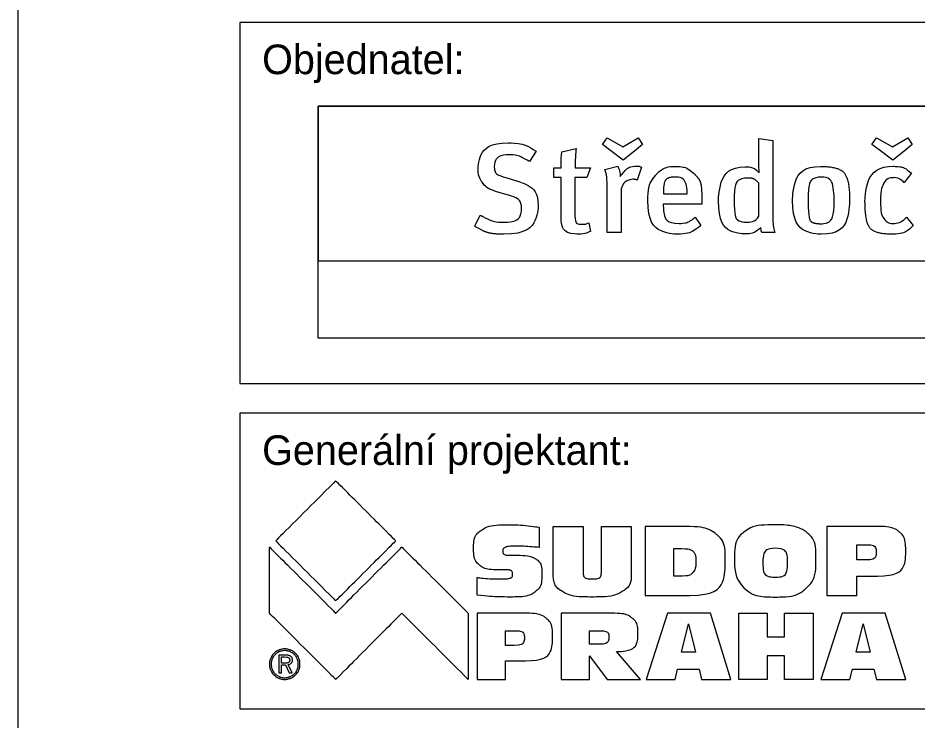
# Model space of a CAD drawing. Extents: x 1619 to 1829, y 760 to 1057.
# Drawn here: x 1618.7 to 1679.4, y 860.7 to 908.2 of the extents above; entities that cross this region are included whole.
import ezdxf

# ---------------------------------------------------------------- set-up
doc = ezdxf.new("R2010")
doc.units = 0
doc.layers.add('102_ZPEVNENI', color=7, linetype='Continuous')
doc.layers.add('120_ZPEVNENI', color=7, linetype='Continuous')

msp = doc.modelspace()

# ---------------------------------------------------------------- linework, layer by layer
at = {"layer": '102_ZPEVNENI'}
for points in [[(1663.73, 873.782), (1661.043, 873.782), (1661.043, 869.128), (1664.09, 869.128)], [(1676.82, 873.782), (1673.326, 873.782), (1673.326, 869.128), (1675.345, 869.128), (1675.345, 870.436), (1676.74, 870.436)], [(1663.563, 870.432), (1662.971, 870.432), (1662.971, 872.286), (1663.498, 872.286)], [(1675.943, 871.522), (1675.345, 871.522), (1675.345, 872.551), (1676.044, 872.551)], [(1653.025, 867.92), (1649.678, 867.92), (1649.678, 863.446), (1651.612, 863.446), (1651.612, 864.703), (1652.949, 864.703)], [(1658.766, 867.92), (1655.36, 867.92), (1655.36, 863.446), (1657.286, 863.446), (1657.286, 865.031), (1658.472, 863.446), (1660.73, 863.446), (1659.105, 865.333)], [(1663.063, 863.446), (1663.232, 864.143), (1664.695, 864.143), (1664.857, 863.446), (1666.838, 863.446), (1665.457, 867.92), (1662.546, 867.92), (1661.11, 863.446), (1663.063, 863.446)], [(1674.876, 863.446), (1675.045, 864.143), (1676.508, 864.143), (1676.67, 863.446), (1678.65, 863.446), (1677.27, 867.92), (1674.358, 867.92), (1672.923, 863.446), (1674.876, 863.446)], [(1663.97, 867.204), (1664.436, 865.28), (1663.498, 865.28), (1663.97, 867.204)], [(1675.783, 867.204), (1676.249, 865.28), (1675.31, 865.28), (1675.783, 867.204)], [(1652.185, 865.748), (1651.612, 865.748), (1651.612, 866.737), (1652.282, 866.737)], [(1657.929, 865.821), (1657.286, 865.821), (1657.286, 866.737), (1657.953, 866.737)], [(1636.709, 865.084), (1636.275, 865.084), (1636.275, 863.899), (1636.453, 863.899), (1636.453, 864.42), (1636.73, 864.42), (1636.98, 863.899), (1637.184, 863.899), (1636.92, 864.445)], [(1636.675, 864.538), (1636.453, 864.538), (1636.453, 864.963), (1636.675, 864.963)]]:
    msp.add_lwpolyline(points, dxfattribs=at)
for points in [[(1636.07, 872.814), (1636.07, 872.814), (1640.125, 876.869), (1640.125, 876.869), (1640.125, 876.869), (1640.125, 876.869), (1644.18, 872.814), (1644.18, 872.814), (1644.18, 872.814), (1644.18, 872.814), (1640.125, 868.759), (1640.125, 868.759), (1640.125, 868.759), (1640.125, 868.759), (1636.07, 872.814), (1636.07, 872.814)], [(1649.678, 869.147), (1650.405, 869.06), (1651.168, 869.016), (1651.968, 869.016), (1651.968, 869.016), (1652.733, 869.016), (1653.272, 869.129), (1653.584, 869.354), (1653.584, 869.354), (1653.899, 869.579), (1654.056, 869.967), (1654.056, 870.519), (1654.056, 870.519), (1654.056, 871.058), (1653.915, 871.418), (1653.631, 871.598), (1653.631, 871.598), (1653.365, 871.759), (1652.824, 871.84), (1652.007, 871.84), (1652.007, 871.84), (1651.616, 871.84), (1651.421, 871.932), (1651.421, 872.117), (1651.421, 872.117), (1651.421, 872.234), (1651.478, 872.319), (1651.593, 872.372), (1651.593, 872.372), (1651.711, 872.425), (1651.916, 872.451), (1652.209, 872.451), (1652.209, 872.451), (1652.706, 872.451), (1653.251, 872.423), (1653.87, 872.366), (1653.87, 872.366), (1653.87, 872.366), (1653.87, 873.738), (1653.87, 873.738), (1653.87, 873.738), (1653.131, 873.842), (1652.439, 873.894), (1651.77, 873.894), (1651.77, 873.894), (1650.927, 873.894), (1650.329, 873.774), (1649.977, 873.534), (1649.977, 873.534), (1649.624, 873.296), (1649.447, 872.916), (1649.447, 872.394), (1649.447, 872.394), (1649.447, 871.815), (1649.573, 871.413), (1649.825, 871.191), (1649.825, 871.191), (1650.08, 870.968), (1650.502, 870.858), (1651.093, 870.863), (1651.093, 870.863), (1651.093, 870.863), (1651.586, 870.863), (1651.586, 870.863), (1651.586, 870.863), (1651.759, 870.863), (1651.885, 870.844), (1651.964, 870.806), (1651.964, 870.806), (1652.043, 870.767), (1652.083, 870.684), (1652.083, 870.557), (1652.083, 870.557), (1652.083, 870.424), (1652.031, 870.337), (1651.928, 870.299), (1651.928, 870.299), (1651.827, 870.261), (1651.657, 870.242), (1651.417, 870.242), (1651.417, 870.242), (1650.673, 870.242), (1650.093, 870.275), (1649.678, 870.341), (1649.678, 870.341), (1649.678, 870.341), (1649.678, 869.147), (1649.678, 869.147)], [(1671.57, 873.62), (1671.154, 873.802), (1670.583, 873.894), (1669.855, 873.894), (1669.855, 873.894), (1668.836, 873.894), (1668.12, 873.726), (1667.705, 873.391), (1667.705, 873.391), (1667.291, 873.057), (1667.084, 872.463), (1667.084, 871.608), (1667.084, 871.608), (1667.084, 870.716), (1667.295, 870.061), (1667.716, 869.643)], [(1654.824, 870.617), (1654.824, 870.046), (1655.033, 869.635), (1655.452, 869.386), (1655.452, 869.386), (1655.871, 869.14), (1656.535, 869.016), (1657.444, 869.016), (1657.444, 869.016), (1658.391, 869.016), (1659.07, 869.14), (1659.482, 869.386), (1659.482, 869.386), (1659.896, 869.633), (1660.103, 870.05), (1660.103, 870.637), (1660.103, 870.637), (1660.103, 870.637), (1660.103, 873.782), (1660.103, 873.782), (1660.103, 873.782), (1660.103, 873.782), (1658.079, 873.782), (1658.079, 873.782), (1658.079, 873.782), (1658.079, 873.782), (1658.079, 870.7), (1658.079, 870.7), (1658.079, 870.7), (1658.079, 870.396), (1657.877, 870.244), (1657.472, 870.244), (1657.472, 870.244), (1657.056, 870.244), (1656.848, 870.401), (1656.848, 870.713), (1656.848, 870.713), (1656.848, 870.713), (1656.848, 873.782), (1656.848, 873.782), (1656.848, 873.782), (1656.848, 873.782), (1654.824, 873.782), (1654.824, 873.782), (1654.824, 873.782), (1654.824, 873.782), (1654.824, 870.617), (1654.824, 870.617)], [(1664.09, 869.128), (1665.668, 869.128), (1666.457, 869.952), (1666.457, 871.599), (1666.457, 871.599), (1666.457, 872.37), (1666.249, 872.926), (1665.833, 873.267), (1665.833, 873.267), (1665.416, 873.61), (1664.716, 873.782), (1663.73, 873.782)], [(1667.716, 869.643), (1668.138, 869.225), (1668.844, 869.016), (1669.834, 869.016), (1669.834, 869.016), (1670.785, 869.016), (1671.481, 869.217), (1671.922, 869.618), (1671.922, 869.618), (1672.365, 870.019), (1672.587, 870.682), (1672.587, 871.608), (1672.587, 871.608), (1672.587, 872.44), (1672.382, 873.029), (1671.973, 873.375), (1671.973, 873.375), (1671.861, 873.469), (1671.726, 873.551), (1671.57, 873.62)], [(1676.74, 870.436), (1678.013, 870.436), (1678.65, 871.006), (1678.65, 872.148), (1678.65, 872.148), (1678.65, 872.76), (1678.504, 873.185), (1678.212, 873.424), (1678.212, 873.424), (1677.922, 873.662), (1677.458, 873.782), (1676.82, 873.782)], [(1635.65, 867.92), (1635.65, 867.92), (1640.125, 863.446), (1640.125, 863.446), (1640.125, 863.446), (1640.125, 863.446), (1644.599, 867.92), (1644.599, 867.92), (1644.599, 867.92), (1644.599, 867.92), (1649.074, 863.446), (1649.074, 863.446), (1649.074, 863.446), (1649.074, 863.446), (1649.074, 867.92), (1649.074, 867.92), (1649.074, 867.92), (1649.074, 867.92), (1644.599, 872.395), (1644.599, 872.395), (1644.599, 872.395), (1644.599, 872.395), (1640.125, 867.92), (1640.125, 867.92), (1640.125, 867.92), (1640.125, 867.92), (1635.65, 872.395), (1635.65, 872.395), (1635.65, 872.395), (1635.65, 872.395), (1635.65, 867.92), (1635.65, 867.92)], [(1663.498, 872.286), (1663.892, 872.286), (1664.153, 872.22), (1664.279, 872.088), (1664.279, 872.088), (1664.404, 871.958), (1664.467, 871.736), (1664.467, 871.423), (1664.467, 871.423), (1664.467, 871.084), (1664.402, 870.834), (1664.271, 870.672), (1664.271, 870.672), (1664.143, 870.512), (1663.907, 870.432), (1663.563, 870.432)], [(1669.841, 872.308), (1670.392, 872.308), (1670.668, 871.999), (1670.668, 871.382), (1670.668, 871.382), (1670.668, 870.703), (1670.392, 870.363), (1669.841, 870.363), (1669.841, 870.363), (1669.282, 870.363), (1669.003, 870.687), (1669.003, 871.334), (1669.003, 871.334), (1669.003, 871.984), (1669.282, 872.308), (1669.841, 872.308)], [(1676.044, 872.551), (1676.457, 872.551), (1676.664, 872.383), (1676.664, 872.046), (1676.664, 872.046), (1676.664, 871.697), (1676.424, 871.522), (1675.943, 871.522)], [(1652.949, 864.703), (1654.169, 864.703), (1654.779, 865.252), (1654.779, 866.35), (1654.779, 866.35), (1654.779, 866.938), (1654.639, 867.347), (1654.359, 867.576), (1654.359, 867.576), (1654.081, 867.805), (1653.636, 867.92), (1653.025, 867.92)], [(1659.105, 865.333), (1660.068, 865.333), (1660.55, 865.754), (1660.55, 866.596), (1660.55, 866.596), (1660.55, 867.057), (1660.414, 867.393), (1660.142, 867.604), (1660.142, 867.604), (1659.87, 867.815), (1659.411, 867.92), (1658.766, 867.92)], [(1667.374, 863.446), (1667.374, 863.446), (1669.296, 863.446), (1669.296, 863.446), (1669.296, 863.446), (1669.296, 863.446), (1669.296, 865.028), (1669.296, 865.028), (1669.296, 865.028), (1669.296, 865.028), (1670.465, 865.028), (1670.465, 865.028), (1670.465, 865.028), (1670.465, 865.028), (1670.465, 863.446), (1670.465, 863.446), (1670.465, 863.446), (1670.465, 863.446), (1672.386, 863.446), (1672.386, 863.446), (1672.386, 863.446), (1672.386, 863.446), (1672.386, 867.92), (1672.386, 867.92), (1672.386, 867.92), (1672.386, 867.92), (1670.465, 867.92), (1670.465, 867.92), (1670.465, 867.92), (1670.465, 867.92), (1670.465, 866.328), (1670.465, 866.328), (1670.465, 866.328), (1670.465, 866.328), (1669.296, 866.328), (1669.296, 866.328), (1669.296, 866.328), (1669.296, 866.328), (1669.296, 867.92), (1669.296, 867.92), (1669.296, 867.92), (1669.296, 867.92), (1667.374, 867.92), (1667.374, 867.92), (1667.374, 867.92), (1667.374, 867.92), (1667.374, 863.446), (1667.374, 863.446)], [(1652.282, 866.737), (1652.678, 866.737), (1652.876, 866.575), (1652.876, 866.251), (1652.876, 866.251), (1652.876, 865.915), (1652.646, 865.748), (1652.185, 865.748)], [(1657.953, 866.737), (1658.38, 866.737), (1658.593, 866.597), (1658.593, 866.316), (1658.593, 866.316), (1658.593, 865.986), (1658.372, 865.821), (1657.929, 865.821)], [(1636.678, 865.504), (1636.539, 865.504), (1636.407, 865.479), (1636.284, 865.428), (1636.284, 865.428), (1636.161, 865.377), (1636.053, 865.304), (1635.958, 865.208), (1635.958, 865.208), (1635.859, 865.108), (1635.783, 864.994), (1635.73, 864.867), (1635.73, 864.867), (1635.677, 864.741), (1635.65, 864.61), (1635.65, 864.475), (1635.65, 864.475), (1635.65, 864.338), (1635.676, 864.208), (1635.728, 864.083), (1635.728, 864.083), (1635.779, 863.959), (1635.854, 863.848), (1635.953, 863.751), (1635.953, 863.751), (1636.05, 863.651), (1636.161, 863.576), (1636.285, 863.524), (1636.285, 863.524), (1636.342, 863.5), (1636.399, 863.482), (1636.458, 863.469)], [(1637.596, 864.471), (1637.596, 864.344), (1637.574, 864.227), (1637.53, 864.12), (1637.53, 864.12), (1637.485, 864.012), (1637.42, 863.916), (1637.335, 863.833), (1637.335, 863.833), (1637.244, 863.745), (1637.143, 863.678), (1637.03, 863.631), (1637.03, 863.631), (1636.917, 863.584), (1636.8, 863.561), (1636.678, 863.561), (1636.678, 863.561), (1636.557, 863.561), (1636.441, 863.584), (1636.331, 863.63), (1636.331, 863.63), (1636.22, 863.676), (1636.121, 863.743), (1636.033, 863.83), (1636.033, 863.83), (1635.945, 863.918), (1635.879, 864.017), (1635.832, 864.127), (1635.832, 864.127), (1635.786, 864.237), (1635.763, 864.353), (1635.763, 864.474), (1635.763, 864.474), (1635.763, 864.594), (1635.786, 864.71), (1635.834, 864.822), (1635.834, 864.822), (1635.881, 864.934), (1635.949, 865.035), (1636.038, 865.125), (1636.038, 865.125), (1636.124, 865.211), (1636.222, 865.277), (1636.331, 865.322), (1636.331, 865.322), (1636.441, 865.366), (1636.556, 865.389), (1636.678, 865.389), (1636.678, 865.389), (1636.803, 865.389), (1636.923, 865.366), (1637.034, 865.319), (1637.034, 865.319), (1637.147, 865.274), (1637.246, 865.207), (1637.335, 865.12), (1637.335, 865.12), (1637.419, 865.035), (1637.484, 864.937), (1637.529, 864.826), (1637.529, 864.826), (1637.574, 864.714), (1637.596, 864.596), (1637.596, 864.471)], [(1636.458, 863.469), (1636.529, 863.453), (1636.603, 863.446), (1636.678, 863.446), (1636.678, 863.446), (1636.814, 863.446), (1636.945, 863.472), (1637.072, 863.525), (1637.072, 863.525), (1637.199, 863.578), (1637.312, 863.654), (1637.412, 863.753), (1637.412, 863.753), (1637.509, 863.849), (1637.583, 863.958), (1637.633, 864.08), (1637.633, 864.08), (1637.684, 864.203), (1637.709, 864.335), (1637.709, 864.475), (1637.709, 864.475), (1637.709, 864.615), (1637.683, 864.747), (1637.632, 864.871), (1637.632, 864.871), (1637.581, 864.996), (1637.508, 865.107), (1637.412, 865.202), (1637.412, 865.202), (1637.315, 865.3), (1637.205, 865.375), (1637.079, 865.427), (1637.079, 865.427), (1636.954, 865.478), (1636.82, 865.504), (1636.678, 865.504)], [(1636.675, 864.963), (1636.795, 864.963), (1636.882, 864.946), (1636.935, 864.912), (1636.935, 864.912), (1636.988, 864.878), (1637.015, 864.822), (1637.015, 864.744), (1637.015, 864.744), (1637.015, 864.67), (1636.99, 864.616), (1636.939, 864.585), (1636.939, 864.585), (1636.889, 864.554), (1636.801, 864.538), (1636.675, 864.538)], [(1636.92, 864.445), (1637.005, 864.457), (1637.073, 864.491), (1637.124, 864.548), (1637.124, 864.548), (1637.174, 864.604), (1637.199, 864.673), (1637.199, 864.757), (1637.199, 864.757), (1637.199, 864.868), (1637.16, 864.951), (1637.079, 865.004), (1637.079, 865.004), (1636.999, 865.057), (1636.875, 865.084), (1636.709, 865.084)]]:
    msp.add_open_spline(points, degree=3, dxfattribs=at)
at = {"layer": '120_ZPEVNENI'}
for p, q in [((1813.65, 907.867), (1633.65, 907.867)), ((1633.65, 907.867), (1633.65, 883.446)), ((1655.405, 899.103), (1656.379, 899.336)), ((1653.671, 899.155), (1653.223, 898.456)), ((1658.317, 897.913), (1659.19, 898.136)), ((1660.802, 898.077), (1660.509, 897.196)), ((1679.032, 897.662), (1678.557, 897.032)), ((1651.635, 897.368), (1652.343, 897.161)), ((1668.727, 894.771), (1668.727, 896.99)), ((1651.799, 896.186), (1651.161, 896.367)), ((1662.273, 896.281), (1663.888, 896.281)), ((1649.522, 894.08), (1649.9, 894.84)), ((1664.429, 894.702), (1664.802, 894.124)), ((1678.704, 894.702), (1679.153, 894.124)), ((1657.234, 894.305), (1657.354, 893.735)), ((1669.804, 893.658), (1668.934, 893.658)), ((1633.65, 883.446), (1813.65, 883.446))]:
    msp.add_line(p, q, dxfattribs=at)
for points in [[(1618.65, 759.931), (1828.65, 759.931), (1828.65, 1056.931), (1618.65, 1056.931)], [(1638.95, 902.209), (1727.871, 902.209), (1727.871, 886.517), (1638.95, 886.517)], [(1633.65, 861.446), (1813.65, 861.446), (1813.65, 881.446), (1633.65, 881.446)]]:
    msp.add_lwpolyline(points, close=True, dxfattribs=at)
for points in [[(1717.41, 891.748), (1727.871, 902.209), (1638.95, 902.209), (1638.95, 891.748), (1717.41, 891.748)], [(1660.328, 899.163), (1659.553, 898.543), (1658.722, 899.172), (1658.152, 899.604), (1658.463, 900.069), (1659.541, 899.441), (1660.579, 900.069), (1660.862, 899.604), (1660.328, 899.163)], [(1668.727, 898.422), (1668.727, 900.019), (1669.666, 899.871), (1669.666, 895.176)], [(1678.548, 899.163), (1677.772, 898.543), (1676.942, 899.172), (1676.373, 899.604), (1676.684, 900.069), (1677.762, 899.441), (1678.798, 900.069), (1679.083, 899.604), (1678.548, 899.163)], [(1655.362, 894.667), (1655.362, 897.368), (1654.878, 897.368), (1654.878, 898.024), (1655.362, 898.024)], [(1656.303, 898.024), (1657.346, 898.024), (1657.096, 897.368), (1656.293, 897.368), (1656.293, 894.917)], [(1659.423, 896.609), (1659.423, 893.658), (1658.472, 893.658), (1658.472, 896.738)], [(1664.871, 895.781), (1664.871, 895.582), (1662.264, 895.582), (1662.264, 895.513)]]:
    msp.add_lwpolyline(points, dxfattribs=at)
for points, degree in [([(1649.754, 897.955), (1649.754, 897.955), (1649.754, 899.008), (1650.582, 899.725), (1651.782, 899.725)], 3), ([(1651.782, 899.725), (1651.782, 899.725), (1652.463, 899.725), (1653.145, 899.526), (1653.671, 899.155)], 3), ([(1656.379, 899.336), (1656.379, 899.336), (1656.337, 898.983), (1656.303, 898.456), (1656.303, 898.024)], 3), ([(1651.818, 898.913), (1651.818, 898.913), (1651.23, 898.913), (1650.841, 898.594), (1650.841, 898.102)], 3), ([(1653.223, 898.456), (1653.223, 898.456), (1652.671, 898.785), (1652.292, 898.913), (1651.818, 898.913)], 3), ([(1655.362, 898.024), (1655.362, 898.024), (1655.362, 898.395), (1655.362, 898.776), (1655.405, 899.103)], 3), ([(1659.19, 898.136), (1659.19, 898.136), (1659.292, 897.939), (1659.352, 897.688), (1659.352, 897.447)], 3), ([(1659.352, 897.447), (1659.352, 897.447), (1659.697, 897.921), (1660.043, 898.146), (1660.466, 898.146)], 3), ([(1660.466, 898.146), (1660.466, 898.146), (1660.604, 898.146), (1660.691, 898.129), (1660.802, 898.077)], 3), ([(1661.764, 897.542), (1661.764, 897.542), (1662.118, 897.947), (1662.55, 898.129), (1663.102, 898.129)], 3), ([(1663.102, 898.129), (1663.102, 898.129), (1663.533, 898.129), (1663.931, 898.016), (1664.302, 897.68)], 3), ([(1668.752, 897.705), (1668.752, 897.705), (1668.752, 897.705), (1668.727, 898.042), (1668.727, 898.422)], 3), ([(1671.005, 895.833), (1671.005, 895.833), (1671.005, 897.231), (1671.756, 898.129), (1672.913, 898.129)], 3), ([(1672.913, 898.129), (1674.156, 898.129), (1674.863, 897.205), (1674.863, 895.824)], 2), ([(1675.899, 895.788), (1675.899, 895.788), (1675.899, 897.376), (1676.848, 898.136), (1677.823, 898.136)], 3), ([(1677.823, 898.136), (1677.823, 898.136), (1678.297, 898.136), (1678.643, 898.024), (1679.032, 897.662)], 3), ([(1650.004, 897.084), (1650.004, 897.084), (1649.84, 897.325), (1649.754, 897.61), (1649.754, 897.955)], 3), ([(1650.841, 898.102), (1650.841, 898.102), (1650.841, 897.732), (1651.047, 897.542), (1651.635, 897.368)], 3), ([(1658.472, 896.738), (1658.472, 896.738), (1658.472, 897.291), (1658.413, 897.645), (1658.317, 897.913)], 3), ([(1661.221, 895.833), (1661.221, 895.833), (1661.221, 896.601), (1661.383, 897.11), (1661.764, 897.542)], 3), ([(1664.302, 897.68), (1664.681, 897.334), (1664.871, 896.799), (1664.871, 895.781)], 2), ([(1665.999, 895.798), (1665.999, 895.798), (1665.999, 897.17), (1666.759, 898.102), (1667.811, 898.102)], 3), ([(1667.811, 898.102), (1667.811, 898.102), (1668.181, 898.102), (1668.484, 897.982), (1668.752, 897.705)], 3), ([(1651.161, 896.367), (1651.161, 896.367), (1650.617, 896.522), (1650.229, 896.747), (1650.004, 897.084)], 3), ([(1652.343, 897.161), (1652.343, 897.161), (1653.206, 896.911), (1653.809, 896.359), (1653.809, 895.461)], 3), ([(1660.241, 897.256), (1660.241, 897.256), (1659.844, 897.256), (1659.508, 896.963), (1659.423, 896.609)], 3), ([(1660.509, 897.196), (1660.415, 897.231), (1660.345, 897.256), (1660.241, 897.256)], 2), ([(1663.102, 897.412), (1662.569, 897.412), (1662.273, 896.99), (1662.273, 896.281)], 2), ([(1663.888, 896.281), (1663.888, 896.281), (1663.888, 896.99), (1663.576, 897.412), (1663.102, 897.412)], 3), ([(1667.933, 897.342), (1667.933, 897.342), (1667.328, 897.342), (1667.05, 896.859), (1667.05, 895.806)], 3), ([(1668.727, 896.99), (1668.511, 897.222), (1668.251, 897.342), (1667.933, 897.342)], 2), ([(1672.921, 897.412), (1672.921, 897.412), (1672.318, 897.412), (1672.057, 896.954), (1672.057, 895.893)], 3), ([(1673.817, 895.806), (1673.817, 895.806), (1673.817, 897.041), (1673.473, 897.412), (1672.921, 897.412)], 3), ([(1677.133, 896.928), (1677.133, 896.928), (1677.002, 896.661), (1676.953, 896.255), (1676.953, 895.712)], 3), ([(1677.823, 897.368), (1677.823, 897.368), (1677.521, 897.368), (1677.27, 897.212), (1677.133, 896.928)], 3), ([(1678.557, 897.032), (1678.557, 897.032), (1678.297, 897.265), (1678.074, 897.368), (1677.823, 897.368)], 3), ([(1652.688, 895.297), (1652.688, 895.297), (1652.688, 895.738), (1652.411, 896.014), (1651.799, 896.186)], 3), ([(1663.232, 893.546), (1663.232, 893.546), (1661.997, 893.546), (1661.221, 894.434), (1661.221, 895.833)], 3), ([(1667.786, 893.563), (1667.786, 893.563), (1666.672, 893.563), (1665.999, 894.434), (1665.999, 895.798)], 3), ([(1667.05, 895.806), (1667.05, 895.806), (1667.05, 894.84), (1667.242, 894.356), (1667.958, 894.356)], 3), ([(1672.929, 893.546), (1672.929, 893.546), (1671.747, 893.546), (1671.005, 894.434), (1671.005, 895.833)], 3), ([(1672.057, 895.893), (1672.057, 894.624), (1672.378, 894.253), (1672.947, 894.253)], 2), ([(1674.863, 895.824), (1674.863, 895.824), (1674.863, 894.417), (1674.111, 893.546), (1672.929, 893.546)], 3), ([(1672.947, 894.253), (1672.947, 894.253), (1673.508, 894.253), (1673.817, 894.711), (1673.817, 895.806)], 3), ([(1677.755, 893.546), (1676.563, 893.546), (1675.899, 894.383), (1675.899, 895.788)], 2), ([(1676.953, 895.712), (1676.953, 895.712), (1676.953, 895.116), (1677.046, 894.737), (1677.245, 894.521)], 3), ([(1653.809, 895.461), (1653.809, 895.461), (1653.809, 894.468), (1653.007, 893.546), (1651.48, 893.546)], 3), ([(1651.512, 894.348), (1651.512, 894.348), (1652.248, 894.348), (1652.688, 894.702), (1652.688, 895.297)], 3), ([(1662.264, 895.513), (1662.264, 895.513), (1662.264, 894.909), (1662.49, 894.271), (1663.344, 894.271)], 3), ([(1669.666, 895.176), (1669.666, 895.176), (1669.666, 894.313), (1669.72, 893.873), (1669.804, 893.658)], 3), ([(1649.9, 894.84), (1649.9, 894.84), (1650.435, 894.529), (1650.91, 894.348), (1651.512, 894.348)], 3), ([(1656.501, 893.546), (1656.501, 893.546), (1655.655, 893.546), (1655.362, 894.047), (1655.362, 894.667)], 3), ([(1656.293, 894.917), (1656.293, 894.917), (1656.293, 894.374), (1656.414, 894.219), (1656.828, 894.219)], 3), ([(1663.344, 894.271), (1663.344, 894.271), (1663.748, 894.271), (1664.103, 894.417), (1664.429, 894.702)], 3), ([(1667.958, 894.356), (1667.958, 894.356), (1668.311, 894.356), (1668.598, 894.555), (1668.727, 894.771)], 3), ([(1677.245, 894.521), (1677.245, 894.521), (1677.383, 894.365), (1677.59, 894.271), (1677.823, 894.271)], 3), ([(1677.823, 894.271), (1677.823, 894.271), (1678.126, 894.271), (1678.42, 894.417), (1678.704, 894.702)], 3), ([(1651.48, 893.546), (1650.799, 893.546), (1650.108, 893.727), (1649.522, 894.08)], 2), ([(1656.828, 894.219), (1656.828, 894.219), (1656.958, 894.219), (1657.069, 894.244), (1657.234, 894.305)], 3), ([(1664.802, 894.124), (1664.802, 894.124), (1664.345, 893.735), (1663.819, 893.546), (1663.232, 893.546)], 3), ([(1668.856, 893.994), (1668.856, 893.994), (1668.562, 893.702), (1668.217, 893.563), (1667.786, 893.563)], 3), ([(1668.934, 893.658), (1668.889, 893.752), (1668.882, 893.813), (1668.856, 893.994)], 2), ([(1679.153, 894.124), (1679.153, 894.124), (1678.754, 893.727), (1678.341, 893.546), (1677.755, 893.546)], 3), ([(1657.354, 893.735), (1657.354, 893.735), (1657.069, 893.606), (1656.793, 893.546), (1656.501, 893.546)], 3), ([(1722.641, 886.517), (1722.641, 886.517), (1717.41, 891.748), (1717.41, 891.748), (1717.41, 891.748), (1717.41, 891.748), (1638.95, 891.748), (1638.95, 891.748), (1638.95, 891.748), (1638.95, 891.748), (1638.95, 886.517), (1638.95, 886.517), (1638.95, 886.517), (1638.95, 886.517), (1722.641, 886.517), (1722.641, 886.517)], 3)]:
    msp.add_open_spline(points, degree=degree, dxfattribs=at)

# ---------------------------------------------------------------- texts
for s, p in [('Objednatel:', (1635.15, 904.367)), ('Generální projektant:', (1635.15, 877.946))]:
    msp.add_text(s, height=2, dxfattribs=at).set_placement(p)

doc.saveas('drawing.dxf')
